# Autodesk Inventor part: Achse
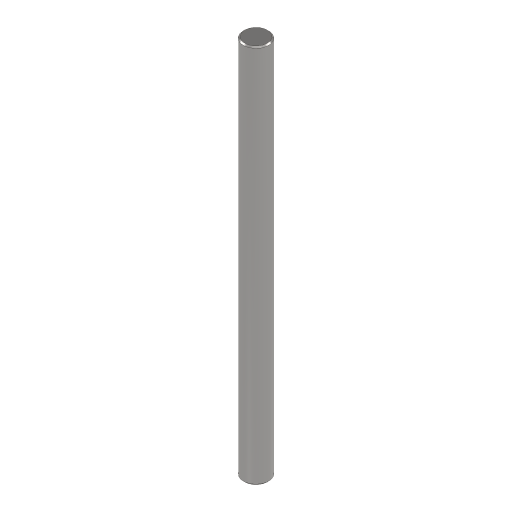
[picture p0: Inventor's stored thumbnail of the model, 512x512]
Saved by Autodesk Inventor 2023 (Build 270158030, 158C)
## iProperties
Created: 2022-09
Part Number: Achse
Material: Edelstahl
Document SubType Name: Modeling
Designer: Christoph Steinmann
Density: 8 g/cm^3
Appearance: Halbpoliert
Mass: 6.03186 g
Surface Area: 7.79115 cm^2
Volume: 0.753982 cm^3
Author: Christoph Steinmann
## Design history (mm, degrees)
sketch "Skizze1"
  geometry: C1 r 2 at (0, 0); 1 further point
  constraints: 1 centre point, 1 coincident
  dimensions: "d0" = 4 diameter of C1
extrude "Extrusion1" new body sketch "Skizze1" distance "d1" = 60; taper "d2" = 0 deg
chamfer "Fase1" distance "d3" = 0.2; stored, may be unused: second distance "d4" = 2, angle "d5" = 45 deg
node "Volumenkörper1"
